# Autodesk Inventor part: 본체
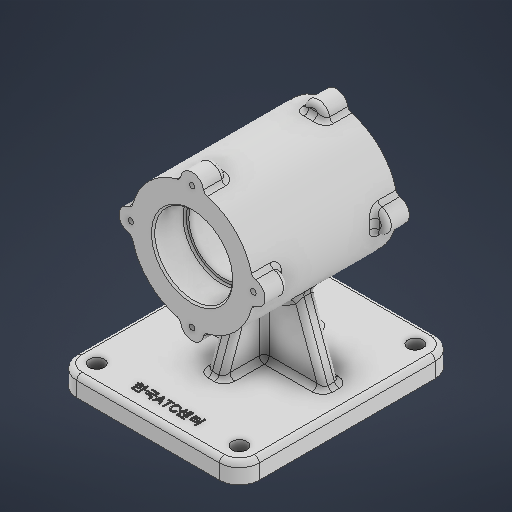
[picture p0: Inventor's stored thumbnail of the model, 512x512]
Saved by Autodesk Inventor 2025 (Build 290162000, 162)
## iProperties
Created: 2025-08
Part Number: 본체
Material: 일반
Document SubType Name: Modeling
Designer: infra17
Density: 1 g/cm^3
Appearance: 기본값
Author: infra17
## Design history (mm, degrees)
sketch "스케치1"
  geometry: L1 (55, 65)-(-55, 65); L2 (-55, 65)-(-55, -65); L3 (-55, -65)-(55, -65); L4 (55, -65)-(55, 65); 1 further point
  constraints: 8 end point, 3 perpendicular, 1 horizontal
  dimensions: "d0" = 130 distance between parallel lines of L3 L1; "d1" = 65 distance from line of L3 point (0, 0) (= 0.5 x d0); "d3" = 110 distance between parallel lines of L2 L4; "d4" = 55 distance from line of point (0, 0) L4
extrude "돌출1" new body sketch "스케치1" distance "d5" = 12; taper "d6" = 0 deg
sketch "스케치2"
  geometry: 1 further point
sketch "스케치4"
  geometry: L1 (119, 38.5)-(105.5, 38.5); L2 (105.5, 38.5)-(105.5, 19.5); L3 (105.5, 19.5)-(103, 19.5); L4 (103, 19.5)-(103, -29.5); L5 (103, -29.5)-(105.5, -29.5); L6 (105.5, -29.5)-(105.5, -48.5); L7 (105.5, -48.5)-(119, -48.5); L8 (119, -48.5)-(119, 38.5); L9 (0, 65)-(12, 65) reference; L10 (82, 34.448)-(82, -42.135); L11 (0, 65)-(0, -65) reference; 4 further points
  constraints: 18 end point, 6 perpendicular, 3 midpoint, 2 point on line, 1 horizontal, 1 vertical
  dimensions: "d9" = 19 distance from line of point (104.25, 19.5) L1; "d10" = 87 distance from line of point (112.25, -48.5) L1; "d11" = 19 distance of L5.end L6.end; "d13" = 70 distance from line of point (119, -5) L9; "d14" = 82 distance between parallel lines of L11 L10; "d15" = 21 distance between parallel lines of L10 L4; "d16" = 23.5 distance between parallel lines of L10 L6; "d17" = 37 distance between parallel lines of L10 L8
revolve "회전1" sketch "스케치4" stored, may be unused: angle "d18" = 90 deg
sketch "스케치5"
  geometry: C1 r 7 at (0, 37); C2 r 7 at (-37, 0); C3 r 7 at (0, -37); C4 r 7 at (37, 0); 2 further points
  constraints: 4 centre point, 2 vertical alignment, 10 other
  dimensions: "d19" = 14 diameter of C1; "d22" = 360 deg dimension on point (0, 0) C1.centre (derived)
extrude "돌출2" join sketch "스케치5" distance "d24" = 14; taper "d25" = 0 deg
sketch "스케치6"
  geometry: C1 r 7 at (0, 37); C2 r 7 at (-37, 0); C3 r 7 at (0, -37); C4 r 7 at (37, 0); 4 further points
  constraints: 4 centre point, 1 vertical alignment, 11 other
  dimensions: "d26" = 14 diameter of C1; "d29" = 360 deg dimension on point (0, 0) C1.centre (derived)
extrude "돌출3" join sketch "스케치6" distance "d31" = 14; taper "d32" = 0 deg
chamfer "모따기1" distance "d33" = 1; stored, may be unused: second distance "d34" = 2, angle "d35" = 45 deg
sketch "스케치7"
  geometry: L1 (0, 37)-(0, 74); L2 (-55, -33)-(55, -33) reference; L3 (-55, -45)-(55, -45) reference; 7 further points
  constraints: 2 end point, 2 midpoint, 1 coincident, 1 vertical, 1 vertical alignment, 5 other
  dimensions: "d36" = 37 distance of L1.start L1.end; "d37" = 82 distance of point (0, -45) L1.start; "d40" = 360 deg dimension on L1.start point (0, 74) (derived)
hole "구멍1" sketch "스케치7" at (0, 74), (37, 37), (0, 0), (-37, 37) diameter "d42" = 3.242; stored, may be unused: countersink angle "d46" = 90 deg, drill point angle "d48" = 118 deg; dims "d43" = 8, "d44" = 8, "d45" = 4.4, "d47" = 10
sketch "스케치8"
  geometry: L1 (0, -37)-(0, 0); L2 (-55, -107)-(55, -107) reference; L3 (-55, -119)-(55, -119) reference; L4 (0, -37)-(-37, -37); L5 (0, -37)-(0, -74); L6 (0, -37)-(37, -37); 7 further points
  constraints: 8 end point, 6 coincident, 2 midpoint, 1 vertical, 1 vertical alignment, 15 other
  dimensions: "d49" = 82 distance of point (0, -119) L1.start; "d50" = 37 distance of L1.start L1.end; "d53" = 360 deg dimension on L1.start L1.end (derived)
hole "구멍2" sketch "스케치8" at (0, 0), (37, -37), (0, -74), (-37, -37) diameter "d55" = 3.242; stored, may be unused: countersink angle "d59" = 90 deg, drill point angle "d61" = 118 deg; dims "d56" = 8, "d57" = 4, "d58" = 2, "d60" = 10
sketch "스케치9" dims "d0" = 130, "d1" = 65 (= 0.5 x d0), "d3" = 110, "d4" = 55
  geometry: L1 (-4.685, -59.739)-(4.685, -59.739); L2 (4.685, -59.739)-(4.685, -46.261); L3 (4.685, -46.261)-(-4.685, -46.261); L4 (-4.685, -46.261)-(-4.685, -59.739); L5 (-55, -65)-(55, -65) reference; 7 further points
  constraints: 6 midpoint, 2 vertical alignment, 2 other
  dimensions: "d101" = 12 vertical distance of point (0, -65) point (4.685, -53)
sketch "스케치10"
  geometry: L1 (-55, 65)-(-55, -65) reference; L2 (0, 0)-(-16.743, 0); L3 (-16.743, 0)-(17.214, 0); C1 r 4.5 at (-43, 53); C2 r 4.5 at (43, 53); C3 r 4.5 at (-43, -53); C4 r 4.5 at (43, -53)
  constraints: 4 centre point, 4 end point, 2 symmetric about line, 1 horizontal, 1 horizontal alignment, 1 point on line, 2 other
  dimensions: "d62" = 9 diameter of C1; "d63" = 12 distance from line of L1 C1.centre; "d64" = 9 diameter of C2; "d65" = 86 distance of C2.centre C1.centre; "d66" = 53 distance from line of L2 C1.centre
extrude "돌출4" cut sketch "스케치10" distance "d67" = 14; taper "d68" = 0 deg
fillet "모깎기1" dims "d69" = 12
sketch "스케치11"
  geometry: L1 (12, 53)-(12, -53) reference; L2 (12, -35)-(49.407, -21.385); L3 (12, 25)-(54.435, 9.555); L4 (0, 65)-(12, 65) reference; L5 (12, 25)-(12, -35); L6 (54.435, 9.555)-(49.407, -21.385); 1 further point
  constraints: 8 end point, 2 point on line, 2 vertical alignment, 1 collinear
  dimensions: "d70" = 110 deg angle of L1 L2; "d71" = 110 deg angle of L1 L3; "d72" = 60 distance of L2.start L3.start; "d73" = 42.43456 horizontal distance of L3.start L3.end; "d74" = 37.40716 horizontal distance of L2.start L2.end; "d75" = 40 distance from line of L4 L3.start
extrude "돌출5" join sketch "스케치11" stored distance "d76" = 10; taper "d77" = 0 deg
node "작업 평면1"
sketch "스케치12"
  geometry: L1 (17.851, 55.55)-(2, 12); L2 (86, 12)-(0, 12) reference; L3 (68.002, 55.954)-(84, 12); L4 (-12, 0)-(-12, 12) reference; L5 (98, 12)-(98, 0) reference; L6 (-12, 12)-(0, 12) reference; L7 (86, 12)-(98, 12) reference; 1 further point
  constraints: 4 end point, 2 point on line
  dimensions: "d79" = 14 distance from line of L4 L1.end; "d80" = 14 distance from line of L5 L3.end; "d81" = 110 deg angle of L6 L1; "d82" = 110 deg angle of L7 L3; "d83" = 46.34494 distance of L1.start L1.end; "d84" = 46.77482 distance of L3.start L3.end
feature "리브1" dims "d85" = 1, "d86" = 10, "d87" = 0, "d88" = 0, "d89" = 1, "d90" = 1
feature "리브2" dims "d91" = 1, "d92" = 10, "d93" = 0, "d94" = 0, "d95" = 1, "d96" = 1
fillet "모깎기2" dims "d97" = 3
fillet "모깎기3" dims "d98" = 3
fillet "모깎기4" dims "d99" = 1
fillet "모깎기5" dims "d100" = 3
feature "엠보싱1" dims "d9" = 19, "d10" = 87, "d11" = 19, "d13" = 70, "d14" = 82, "d15" = 21, "d16" = 23.5, "d17" = 37, "d102" = 0.5, "d103" = 0
node "솔리드1"
node "스케치 - 원형 패턴1" dims "d22" = 360 deg (derived)
node "스케치 - 원형 패턴2" dims "d29" = 360 deg (derived)
node "스케치 - 원형 패턴3" dims "d40" = 360 deg (derived)
node "스케치 - 원형 패턴4" dims "d53" = 360 deg (derived)
feature "A9D066F2-1C7D-4E18-AEED-F7BC21143FA4" dims "d42" = 3.242, "d43" = 8, "d44" = 8, "d45" = 4.4, "d46" = 90 deg, "d47" = 10, "d48" = 118 deg
